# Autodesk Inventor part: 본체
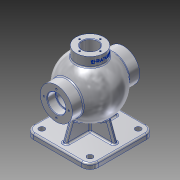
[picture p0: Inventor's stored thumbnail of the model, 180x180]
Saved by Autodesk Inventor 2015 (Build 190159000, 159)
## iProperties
Created: 2025-08
Part Number: 본체
Material: 알루미늄 6061
Document SubType Name: Modeling
Designer: USER
Density: 2.7 g/cm^3
Appearance: 알루미늄 - 평지
Mass: 1515.64 g
Surface Area: 1173.65 cm^2
Volume: 561.348 cm^3
Author: USER
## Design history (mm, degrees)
sketch "스케치1"
  geometry: L1 (-62.5, 62.5)-(62.5, 62.5); L2 (62.5, 62.5)-(62.5, -62.5); L3 (62.5, -62.5)-(-62.5, -62.5); L4 (-62.5, -62.5)-(-62.5, 62.5); L5 (-62.5, 62.5)-(62.5, -62.5); L6 (62.5, 62.5)-(-62.5, -62.5); 1 further point
  constraints: 12 end point, 2 midpoint, 2 parallel, 1 horizontal, 1 perpendicular
  dimensions: "d0" = 125 distance of L2.end L3.end; "d1" = 125 distance of L1.end L2.end
extrude "돌출1" new body sketch "스케치1" distance "d2" = 10; taper "d3" = 0 deg
sketch "스케치3"
  geometry: L1 (62.5, 10)-(62.5, 0) reference; L2 (62.5, 0)-(-62.5, 0) reference; L3 (-62.5, 0)-(-62.5, 10) reference; L4 (-62.5, 10)-(62.5, 10) reference; L5 (54, 85)-(-54, 85); A1 r 54 centre (0, 85) between (54, 85) and (-54, 85); A2 r 44 centre (0, 85) between (44, 85) and (-44, 85); 2 further points
  constraints: 4 point on circle, 2 centre point, 2 end point, 2 point on line, 1 coincident, 1 horizontal, 1 midpoint, 1 vertical alignment
  dimensions: "d8" = 108 diameter of A1; "d9" = 85 distance of point (0, 0) A1.centre; "d10" = 88 diameter of A2; "d11" = 108 distance of L5.start L5.end
revolve "회전1" sketch "스케치3" stored, may be unused: angle "d12" = 90 deg
node "작업 평면1"
node "작업 평면2"
sketch "스케치6"
  geometry: C1 r 27 at (0, 0); 1 further point
  constraints: 1 centre point, 1 coincident
  dimensions: "d27" = 54 diameter of C1
extrude "돌출3" join sketch "스케치6" stored distance "d28" = 10; taper "d29" = 0 deg
hole "구멍2" diameter "d32" = 30; stored, may be unused: countersink angle "d36" = 90 deg, drill point angle "d38" = 0 deg; dims "d30" = 10, "d31" = 10, "d33" = 6, "d34" = 26, "d35" = 16, "d37" = 8
sketch "스케치7"
  geometry: L1 (-62.5, 62.5)-(62.5, 62.5) reference; L2 (62.5, 62.5)-(62.5, -62.5) reference; L3 (62.5, -62.5)-(-62.5, -62.5) reference; L4 (-62.5, -62.5)-(-62.5, 62.5) reference; L5 (-4, -50.5)-(4, -50.5); L6 (4, -50.5)-(4, 50.5); L7 (4, 50.5)-(-4, 50.5); L8 (-4, 50.5)-(-4, -50.5); L9 (-4, -50.5)-(4, 50.5); L10 (4, -50.5)-(-4, 50.5); L11 (-50.5, 4)-(50.5, 4); L12 (50.5, 4)-(50.5, -4); L13 (50.5, -4)-(-50.5, -4); L14 (-50.5, -4)-(-50.5, 4); L15 (-50.5, 4)-(50.5, -4); L16 (50.5, 4)-(-50.5, -4); 1 further point
  constraints: 24 end point, 4 midpoint, 4 parallel, 2 horizontal, 2 perpendicular
  dimensions: "d39" = 12 distance between parallel lines of L7 L1; "d40" = 4 distance from line of L6 point (0, 0); "d41" = 12 distance between parallel lines of L2 L12; "d42" = 4 distance from line of point (0, 0) L11
extrude "돌출4" join sketch "스케치7" stored distance "d43" = 10; taper "d44" = 0 deg
sketch "스케치8"
  geometry: L1 (-4, 50.5)-(4, 50.5) reference; L2 (4, 50.5)-(4, 4) reference; L3 (4, 4)-(50.5, 4) reference; L4 (50.5, 4)-(50.5, -4) reference; L5 (50.5, -4)-(4, -4) reference; L6 (4, -4)-(4, -50.5) reference; L7 (4, -50.5)-(-4, -50.5) reference; L8 (-4, -50.5)-(-4, -4) reference; L9 (-4, -4)-(-50.5, -4) reference; L10 (-50.5, -4)-(-50.5, 4) reference; L11 (-50.5, 4)-(-4, 4) reference; L12 (-4, 4)-(-4, 50.5) reference; L13 (-62.5, 62.5)-(62.5, 62.5) reference; L14 (62.5, 62.5)-(62.5, -62.5) reference; L15 (62.5, -62.5)-(-62.5, -62.5) reference; L16 (-62.5, -62.5)-(-62.5, 62.5) reference; C1 r 5.5 at (46.5, 46.5); 1 further point
  constraints: 1 centre point
  dimensions: "d45" = 11 diameter of C1; "d46" = 16 distance from line of C1.centre L13; "d47" = 16 distance from line of L14 C1.centre
extrude "돌출5" cut sketch "스케치8" stored distance "d48" = 10; taper "d49" = 0 deg
fillet "모깎기1" dims "d56" = 16
sketch "스케치11"
  geometry: L1 (0, 0)-(0, 20); C1 r 15 at (0, 0) reference; C2 r 27 at (0, 0) reference; 1 further point
  constraints: 2 end point, 1 vertical
  dimensions: "d69" = 20 distance of L1.start L1.end
hole "구멍4" sketch "스케치11" at (0, 20) diameter "d70" = 3.242; stored, may be unused: countersink angle "d74" = 90 deg, drill point angle "d76" = 118 deg; dims "d71" = 9, "d72" = 4, "d73" = 12, "d75" = 11
feature "면 기울기1" dims angle "d80" = 20 deg
feature "면 기울기2" dims angle "d81" = 20 deg
sketch "스케치15"
  geometry: L1 (-15, 150)-(15, 150) reference; 2 further points
  constraints: 1 vertical alignment, 1 other
  dimensions: "d82" = 9 distance from line of point (0, 141) L1
feature "엠보싱1" sketch "스케치15" dims "d27" = 54, "d83" = 0.5, "d84" = 0
node "작업 평면5"
sketch "스케치17"
  geometry: L1 (-46.5, 0)-(46.5, 0) reference; C1 r 31 at (0, 85); 2 further points
  constraints: 1 centre point, 1 midpoint, 1 vertical alignment
  dimensions: "d86" = 62 diameter of C1; "d87" = 85 distance from line of C1.centre L1
extrude "돌출6" join sketch "스케치17" stored distance "d88" = 130; taper "d89" = 0 deg
hole "구멍5" diameter "d92" = 30; stored, may be unused: countersink angle "d96" = 90 deg, drill point angle "d98" = 0 deg; dims "d90" = 10, "d91" = 10, "d93" = 9, "d94" = 35, "d95" = 16, "d97" = 19.25
sketch "스케치18"
  geometry: 1 further point
sketch "스케치19"
  geometry: 1 further point
sketch "스케치20"
  geometry: L1 (0, 0)-(0, 24); C1 r 17.5 at (0, 0) reference; C2 r 31 at (0, 0) reference; 1 further point
  constraints: 2 end point, 1 vertical
  dimensions: "d99" = 24 distance of L1.start L1.end
hole "구멍6" sketch "스케치20" at (0, 24) diameter "d100" = 3.242; stored, may be unused: countersink angle "d104" = 90 deg, drill point angle "d106" = 118 deg; dims "d101" = 12, "d102" = 35, "d103" = 16, "d105" = 15
chamfer "모따기1" distance "d110" = 1; stored, may be unused: second distance "d111" = 2, angle "d112" = 45 deg
fillet "모깎기2" dims "d113" = 0.6
fillet "모깎기3" dims "d114" = 3
fillet "모깎기4" dims "d115" = 3
fillet "모깎기5" dims "d116" = 3
fillet "모깎기6" dims "d117" = 3
fillet "모깎기7" dims "d118" = 3
fillet "모깎기8" dims "d119" = 3
node "솔리드1"
pattern_linear "직사각형 패턴1" dims "d52" = 93, "d55" = 93
pattern_circular "원형 패턴2" dims angle "d78" = 360 deg
mirror "대칭4"
pattern_circular "원형 패턴3" dims angle "d108" = 360 deg
mirror "대칭5"
node "절단 모서리 투영2"
node "절단 모서리 투영5"
node "절단 모서리 투영6"
node "절단 모서리 투영8"
node "절단 모서리 투영9"
other parameters: "d13" = -54, "d85" = -65
